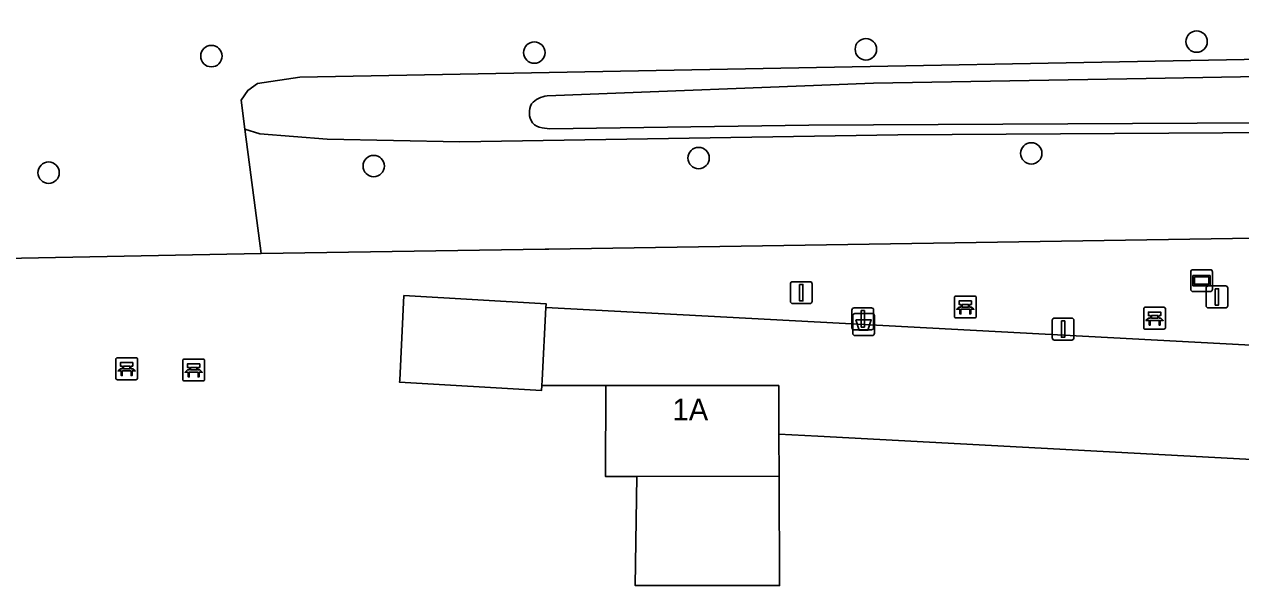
# Model space of a CAD drawing. Extents: x 161758 to 162722, y 384793 to 385405.
# Drawn here: x 162200.5 to 162256.1, y 385324.2 to 385349.9 of the extents above; entities that cross this region are included whole.
import ezdxf

# ---------------------------------------------------------------- set-up
doc = ezdxf.new("R2010")
doc.units = 0
for name, color, linetype in [('IMGEO_Afvalbak', 7, 'Continuous'), ('IMGEO_Bank', 7, 'Continuous'), ('IMGEO_Boom', 7, 'Continuous'), ('IMGEO_Groenvoorziening', 7, 'Continuous'), ('IMGEO_Lichtmast', 7, 'Continuous'), ('IMGEO_Oever', 7, 'Continuous'), ('IMGEO_Pand', 7, 'Continuous'), ('IMGEO_Pand_nummerreeks', 7, 'Continuous'), ('IMGEO_Verklikker', 7, 'Continuous'), ('IMGEO_Voetpad_open', 7, 'Continuous'), ('IMGEO_Waterloop', 7, 'Continuous')]:
    doc.layers.add(name, color=color, linetype=linetype)

msp = doc.modelspace()

# ---------------------------------------------------------------- linework, layer by layer
at = {"layer": 'IMGEO_Afvalbak'}
for p, q in [((162238.462, 385336.656), (162239.252, 385336.656)), ((162239.252, 385336.656), (162238.462, 385336.656)), ((162238.362, 385335.756), (162238.362, 385336.556)), ((162238.362, 385336.556), (162238.362, 385335.756)), ((162239.352, 385336.556), (162239.352, 385335.756)), ((162239.352, 385335.756), (162239.352, 385336.556)), ((162239.252, 385335.656), (162238.462, 385335.656)), ((162238.462, 385335.656), (162239.252, 385335.656))]:
    msp.add_line(p, q, dxfattribs=at)
msp.add_lwpolyline([(162238.505, 385336.37), (162239.209, 385336.37), (162239.06, 385335.9), (162238.654, 385335.9), (162238.505, 385336.37)], dxfattribs=at)
for centre, start, end in [((162238.462, 385336.556), 90, 180), ((162238.462, 385336.556), 90, 180), ((162239.252, 385336.556), 0, 90), ((162239.252, 385336.556), 360, 90), ((162238.462, 385335.756), 180, 270), ((162238.462, 385335.756), 180, 270), ((162239.252, 385335.756), 270, 0), ((162239.252, 385335.756), 270, 0)]:
    msp.add_arc(centre, 0.1, start, end, dxfattribs=at)
at = {"layer": 'IMGEO_Bank'}
for p, q in [((162243.01, 385336.531), (162243.01, 385337.372)), ((162243.01, 385337.372), (162243.01, 385336.531)), ((162243.085, 385337.456), (162243.926, 385337.456)), ((162243.926, 385337.456), (162243.085, 385337.456)), ((162244.01, 385337.381), (162244.01, 385336.54)), ((162244.01, 385336.54), (162244.01, 385337.381)), ((162243.707, 385336.854), (162243.314, 385336.854)), ((162243.319, 385336.962), (162243.319, 385337.068)), ((162243.363, 385337.068), (162243.363, 385336.962)), ((162243.651, 385337.074), (162243.369, 385337.074)), ((162243.369, 385336.956), (162243.651, 385336.956)), ((162243.657, 385336.962), (162243.657, 385337.068)), ((162243.701, 385337.068), (162243.701, 385336.962)), ((162251.66, 385336.021), (162251.66, 385336.862)), ((162251.66, 385336.862), (162251.66, 385336.021)), ((162251.735, 385336.946), (162252.576, 385336.946)), ((162252.576, 385336.946), (162251.735, 385336.946)), ((162252.66, 385336.871), (162252.66, 385336.03)), ((162252.66, 385336.03), (162252.66, 385336.871)), ((162243.935, 385336.456), (162243.094, 385336.456)), ((162243.094, 385336.456), (162243.935, 385336.456)), ((162252.357, 385336.344), (162251.964, 385336.344)), ((162251.969, 385336.452), (162251.969, 385336.558)), ((162252.013, 385336.558), (162252.013, 385336.452)), ((162252.301, 385336.564), (162252.019, 385336.564)), ((162252.019, 385336.446), (162252.301, 385336.446)), ((162252.307, 385336.452), (162252.307, 385336.558)), ((162252.351, 385336.558), (162252.351, 385336.452)), ((162252.585, 385335.946), (162251.744, 385335.946)), ((162251.744, 385335.946), (162252.585, 385335.946)), ((162204.681, 385333.714), (162204.681, 385334.555)), ((162204.681, 385334.555), (162204.681, 385333.714)), ((162204.756, 385334.639), (162205.597, 385334.639)), ((162205.597, 385334.639), (162204.756, 385334.639)), ((162205.681, 385334.564), (162205.681, 385333.723)), ((162205.681, 385333.723), (162205.681, 385334.564)), ((162207.744, 385333.657), (162207.744, 385334.498)), ((162207.744, 385334.498), (162207.744, 385333.657)), ((162207.819, 385334.582), (162208.66, 385334.582)), ((162208.66, 385334.582), (162207.819, 385334.582)), ((162208.744, 385334.507), (162208.744, 385333.666)), ((162208.744, 385333.666), (162208.744, 385334.507)), ((162205.378, 385334.037), (162204.985, 385334.037)), ((162204.99, 385334.145), (162204.99, 385334.251)), ((162205.034, 385334.251), (162205.034, 385334.145)), ((162205.322, 385334.257), (162205.04, 385334.257)), ((162205.04, 385334.139), (162205.322, 385334.139)), ((162205.328, 385334.145), (162205.328, 385334.251)), ((162205.372, 385334.251), (162205.372, 385334.145)), ((162208.441, 385333.98), (162208.048, 385333.98)), ((162208.053, 385334.088), (162208.053, 385334.194)), ((162208.097, 385334.194), (162208.097, 385334.088)), ((162208.385, 385334.2), (162208.103, 385334.2)), ((162208.103, 385334.082), (162208.385, 385334.082)), ((162208.391, 385334.088), (162208.391, 385334.194)), ((162208.435, 385334.194), (162208.435, 385334.088)), ((162205.606, 385333.639), (162204.765, 385333.639)), ((162204.765, 385333.639), (162205.606, 385333.639)), ((162208.669, 385333.582), (162207.828, 385333.582)), ((162207.828, 385333.582), (162208.669, 385333.582))]:
    msp.add_line(p, q, dxfattribs=at)
for points in [[(162243.313, 385337.074), (162243.227, 385337.074), (162243.227, 385337.235), (162243.79, 385337.235), (162243.79, 385337.074), (162243.707, 385337.074)], [(162243.257, 385336.854), (162243.115, 385336.854), (162243.227, 385336.956), (162243.313, 385336.956)], [(162243.307, 385336.847), (162243.307, 385336.64), (162243.264, 385336.64), (162243.264, 385336.847)], [(162243.707, 385336.956), (162243.79, 385336.956), (162243.902, 385336.854), (162243.763, 385336.854)], [(162243.757, 385336.847), (162243.757, 385336.64), (162243.713, 385336.64), (162243.713, 385336.847)], [(162251.963, 385336.564), (162251.877, 385336.564), (162251.877, 385336.725), (162252.44, 385336.725), (162252.44, 385336.564), (162252.357, 385336.564)], [(162251.907, 385336.344), (162251.765, 385336.344), (162251.877, 385336.446), (162251.963, 385336.446)], [(162251.957, 385336.337), (162251.957, 385336.13), (162251.914, 385336.13), (162251.914, 385336.337)], [(162252.357, 385336.446), (162252.44, 385336.446), (162252.552, 385336.344), (162252.413, 385336.344)], [(162252.407, 385336.337), (162252.407, 385336.13), (162252.363, 385336.13), (162252.363, 385336.337)], [(162204.984, 385334.257), (162204.898, 385334.257), (162204.898, 385334.418), (162205.461, 385334.418), (162205.461, 385334.257), (162205.378, 385334.257)], [(162204.928, 385334.037), (162204.786, 385334.037), (162204.898, 385334.139), (162204.984, 385334.139)], [(162204.978, 385334.03), (162204.978, 385333.823), (162204.935, 385333.823), (162204.935, 385334.03)], [(162205.378, 385334.139), (162205.461, 385334.139), (162205.573, 385334.037), (162205.434, 385334.037)], [(162205.428, 385334.03), (162205.428, 385333.823), (162205.384, 385333.823), (162205.384, 385334.03)], [(162207.991, 385333.98), (162207.849, 385333.98), (162207.961, 385334.082), (162208.047, 385334.082)], [(162208.047, 385334.2), (162207.961, 385334.2), (162207.961, 385334.361), (162208.524, 385334.361), (162208.524, 385334.2), (162208.441, 385334.2)], [(162208.041, 385333.973), (162208.041, 385333.766), (162207.998, 385333.766), (162207.998, 385333.973)], [(162208.441, 385334.082), (162208.524, 385334.082), (162208.636, 385333.98), (162208.497, 385333.98)], [(162208.491, 385333.973), (162208.491, 385333.766), (162208.447, 385333.766), (162208.447, 385333.973)]]:
    msp.add_lwpolyline(points, dxfattribs=at)
for centre, radius, start, end in [((162243.088, 385337.378), 0.0779, 92.4484, 184.2845), ((162243.088, 385337.378), 0.0779, 92.4484, 184.2845), ((162243.932, 385337.378), 0.0779, 2.4484, 94.2845), ((162243.932, 385337.378), 0.0779, 2.4484, 94.2845), ((162243.257, 385336.847), 0.00671, 2.8957, 87.1043), ((162243.314, 385336.847), 0.00671, 92.8957, 177.1043), ((162243.312, 385337.067), 0.00671, 2.8957, 87.1043), ((162243.312, 385336.963), 0.00671, 272.8957, 357.1043), ((162243.369, 385337.067), 0.00671, 92.8957, 177.1043), ((162243.369, 385336.963), 0.00671, 182.8957, 267.1043), ((162243.651, 385337.067), 0.00671, 2.8957, 87.1043), ((162243.651, 385336.963), 0.00671, 272.8957, 357.1043), ((162243.708, 385337.067), 0.00671, 92.8957, 177.1043), ((162243.708, 385336.963), 0.00671, 182.8957, 267.1043), ((162243.706, 385336.847), 0.00671, 2.8957, 87.1043), ((162243.763, 385336.847), 0.00671, 92.8957, 177.1043), ((162251.738, 385336.868), 0.0779, 92.4484, 184.2845), ((162251.738, 385336.868), 0.0779, 92.4484, 184.2845), ((162252.582, 385336.868), 0.0779, 2.4484, 94.2845), ((162252.582, 385336.868), 0.0779, 2.4484, 94.2845), ((162243.088, 385336.534), 0.0779, 182.4484, 274.2845), ((162243.088, 385336.534), 0.0779, 182.4484, 274.2845), ((162243.932, 385336.534), 0.0779, 272.4484, 4.2845), ((162243.932, 385336.534), 0.0779, 272.4484, 4.2845), ((162251.907, 385336.337), 0.00671, 2.8957, 87.1043), ((162251.964, 385336.337), 0.00671, 92.8957, 177.1043), ((162251.962, 385336.557), 0.00671, 2.8957, 87.1043), ((162251.962, 385336.453), 0.00671, 272.8957, 357.1043), ((162252.019, 385336.557), 0.00671, 92.8957, 177.1043), ((162252.019, 385336.453), 0.00671, 182.8957, 267.1043), ((162252.301, 385336.557), 0.00671, 2.8957, 87.1043), ((162252.301, 385336.453), 0.00671, 272.8957, 357.1043), ((162252.358, 385336.557), 0.00671, 92.8957, 177.1043), ((162252.358, 385336.453), 0.00671, 182.8957, 267.1043), ((162252.356, 385336.337), 0.00671, 2.8957, 87.1043), ((162252.413, 385336.337), 0.00671, 92.8957, 177.1043), ((162251.738, 385336.024), 0.0779, 182.4484, 274.2845), ((162251.738, 385336.024), 0.0779, 182.4484, 274.2845), ((162252.582, 385336.024), 0.0779, 272.4484, 4.2845), ((162252.582, 385336.024), 0.0779, 272.4484, 4.2845), ((162204.759, 385334.561), 0.0779, 92.4484, 184.2845), ((162204.759, 385334.561), 0.0779, 92.4484, 184.2845), ((162205.603, 385334.561), 0.0779, 2.4484, 94.2845), ((162205.603, 385334.561), 0.0779, 2.4484, 94.2845), ((162207.822, 385334.504), 0.0779, 92.4484, 184.2845), ((162207.822, 385334.504), 0.0779, 92.4484, 184.2845), ((162208.666, 385334.504), 0.0779, 2.4484, 94.2845), ((162208.666, 385334.504), 0.0779, 2.4484, 94.2845), ((162204.928, 385334.03), 0.00671, 2.8957, 87.1043), ((162204.985, 385334.03), 0.00671, 92.8957, 177.1043), ((162204.983, 385334.25), 0.00671, 2.8957, 87.1043), ((162204.983, 385334.146), 0.00671, 272.8957, 357.1043), ((162205.04, 385334.25), 0.00671, 92.8957, 177.1043), ((162205.04, 385334.146), 0.00671, 182.8957, 267.1043), ((162205.322, 385334.25), 0.00671, 2.8957, 87.1043), ((162205.322, 385334.146), 0.00671, 272.8957, 357.1043), ((162205.379, 385334.25), 0.00671, 92.8957, 177.1043), ((162205.379, 385334.146), 0.00671, 182.8957, 267.1043), ((162205.377, 385334.03), 0.00671, 2.8957, 87.1043), ((162205.434, 385334.03), 0.00671, 92.8957, 177.1043), ((162207.991, 385333.973), 0.00671, 2.8957, 87.1043), ((162208.048, 385333.973), 0.00671, 92.8957, 177.1043), ((162208.046, 385334.193), 0.00671, 2.8957, 87.1043), ((162208.046, 385334.089), 0.00671, 272.8957, 357.1043), ((162208.103, 385334.193), 0.00671, 92.8957, 177.1043), ((162208.103, 385334.089), 0.00671, 182.8957, 267.1043), ((162208.385, 385334.193), 0.00671, 2.8957, 87.1043), ((162208.385, 385334.089), 0.00671, 272.8957, 357.1043), ((162208.442, 385334.193), 0.00671, 92.8957, 177.1043), ((162208.442, 385334.089), 0.00671, 182.8957, 267.1043), ((162208.44, 385333.973), 0.00671, 2.8957, 87.1043), ((162208.497, 385333.973), 0.00671, 92.8957, 177.1043), ((162204.759, 385333.717), 0.0779, 182.4484, 274.2845), ((162204.759, 385333.717), 0.0779, 182.4484, 274.2845), ((162205.603, 385333.717), 0.0779, 272.4484, 4.2845), ((162205.603, 385333.717), 0.0779, 272.4484, 4.2845), ((162207.822, 385333.66), 0.0779, 182.4484, 274.2845), ((162207.822, 385333.66), 0.0779, 182.4484, 274.2845), ((162208.666, 385333.66), 0.0779, 272.4484, 4.2845), ((162208.666, 385333.66), 0.0779, 272.4484, 4.2845)]:
    msp.add_arc(centre, radius, start, end, dxfattribs=at)
at = {"layer": 'IMGEO_Boom'}
for centre in [(162254.078, 385349.076), (162209.053, 385348.411), (162223.811, 385348.574), (162238.963, 385348.723), (162246.523, 385343.971), (162216.473, 385343.392), (162231.32, 385343.758), (162201.612, 385343.09)]:
    msp.add_circle(centre, 0.489, dxfattribs=at)
at = {"layer": 'IMGEO_Groenvoorziening'}
for points in [[(162150.256, 385338.217), (162211.326, 385339.4), (162210.576, 385345.078), (162210.407, 385346.397), (162210.716, 385346.847), (162211.162, 385347.162), (162213.09, 385347.455), (162274.995, 385348.608), (162275.287, 385348.966), (162275.287, 385349.716), (162281.73, 385349.862), (162282.898, 385349.07), (162282.9, 385348.722), (162317.058, 385348.931), (162338.302, 385349.603)], [(162280.054, 385345.054), (162240.431, 385344.814), (162220.411, 385344.502), (162214.349, 385344.623), (162211.26, 385344.857), (162210.576, 385345.078), (162211.326, 385339.4), (162224.309, 385339.601), (162224.475, 385339.604), (162280.127, 385340.465)], [(162280.127, 385340.465), (162224.475, 385339.604), (162224.309, 385339.601), (162211.326, 385339.4), (162150.256, 385338.217)], [(162269.369, 385329.305), (162236.772, 385331.057), (162234.99, 385331.156), (162234.998, 385329.231), (162235.019, 385324.236), (162228.418, 385324.247), (162228.492, 385329.215), (162227.065, 385329.212), (162227.072, 385333.378), (162224.155, 385333.38), (162224.142, 385333.149), (162217.656, 385333.521), (162217.662, 385333.622), (162217.855, 385337.476), (162224.348, 385337.109), (162224.339, 385336.928), (162269.685, 385334.516)]]:
    msp.add_lwpolyline(points, dxfattribs=at)
at = {"layer": 'IMGEO_Lichtmast'}
for p, q in [((162235.517, 385337.214), (162235.517, 385338.014)), ((162235.517, 385338.014), (162235.517, 385337.214)), ((162235.617, 385338.114), (162236.407, 385338.114)), ((162236.407, 385338.114), (162235.617, 385338.114)), ((162236.507, 385338.014), (162236.507, 385337.214)), ((162236.507, 385337.214), (162236.507, 385338.014)), ((162254.512, 385337.017), (162254.512, 385337.817)), ((162254.512, 385337.817), (162254.512, 385337.017)), ((162254.612, 385337.917), (162255.402, 385337.917)), ((162255.402, 385337.917), (162254.612, 385337.917)), ((162255.502, 385337.817), (162255.502, 385337.017)), ((162255.502, 385337.017), (162255.502, 385337.817)), ((162236.407, 385337.114), (162235.617, 385337.114)), ((162235.617, 385337.114), (162236.407, 385337.114)), ((162238.329, 385336.018), (162238.329, 385336.818)), ((162238.329, 385336.818), (162238.329, 385336.018)), ((162238.429, 385336.918), (162239.219, 385336.918)), ((162239.219, 385336.918), (162238.429, 385336.918)), ((162239.319, 385336.818), (162239.319, 385336.018)), ((162239.319, 385336.018), (162239.319, 385336.818)), ((162255.402, 385336.917), (162254.612, 385336.917)), ((162254.612, 385336.917), (162255.402, 385336.917)), ((162247.479, 385335.551), (162247.479, 385336.351)), ((162247.479, 385336.351), (162247.479, 385335.551)), ((162247.579, 385336.451), (162248.369, 385336.451)), ((162248.369, 385336.451), (162247.579, 385336.451)), ((162248.469, 385336.351), (162248.469, 385335.551)), ((162248.469, 385335.551), (162248.469, 385336.351)), ((162239.219, 385335.918), (162238.429, 385335.918)), ((162238.429, 385335.918), (162239.219, 385335.918)), ((162248.369, 385335.451), (162247.579, 385335.451)), ((162247.579, 385335.451), (162248.369, 385335.451))]:
    msp.add_line(p, q, dxfattribs=at)
for points in [[(162235.937, 385337.989), (162236.087, 385337.989), (162236.087, 385337.239), (162235.937, 385337.239), (162235.937, 385337.989)], [(162254.932, 385337.792), (162255.082, 385337.792), (162255.082, 385337.042), (162254.932, 385337.042), (162254.932, 385337.792)], [(162238.749, 385336.793), (162238.899, 385336.793), (162238.899, 385336.043), (162238.749, 385336.043), (162238.749, 385336.793)], [(162247.899, 385336.326), (162248.049, 385336.326), (162248.049, 385335.576), (162247.899, 385335.576), (162247.899, 385336.326)]]:
    msp.add_lwpolyline(points, dxfattribs=at)
for centre, start, end in [((162235.617, 385338.014), 90, 180), ((162235.617, 385338.014), 90, 180), ((162236.407, 385338.014), 0, 90), ((162236.407, 385338.014), 360, 90), ((162254.612, 385337.817), 90, 180), ((162254.612, 385337.817), 90, 180), ((162255.402, 385337.817), 0, 90), ((162255.402, 385337.817), 360, 90), ((162235.617, 385337.214), 180, 270), ((162235.617, 385337.214), 180, 270), ((162236.407, 385337.214), 270, 0), ((162236.407, 385337.214), 270, 0), ((162238.429, 385336.818), 90, 180), ((162238.429, 385336.818), 90, 180), ((162239.219, 385336.818), 0, 90), ((162239.219, 385336.818), 360, 90), ((162254.612, 385337.017), 180, 270), ((162254.612, 385337.017), 180, 270), ((162255.402, 385337.017), 270, 0), ((162255.402, 385337.017), 270, 0), ((162247.579, 385336.351), 90, 180), ((162247.579, 385336.351), 90, 180), ((162248.369, 385336.351), 0, 90), ((162248.369, 385336.351), 360, 90), ((162238.429, 385336.018), 180, 270), ((162238.429, 385336.018), 180, 270), ((162239.219, 385336.018), 270, 0), ((162239.219, 385336.018), 270, 0), ((162247.579, 385335.551), 180, 270), ((162247.579, 385335.551), 180, 270), ((162248.369, 385335.551), 270, 0), ((162248.369, 385335.551), 270, 0)]:
    msp.add_arc(centre, 0.1, start, end, dxfattribs=at)
at = {"layer": 'IMGEO_Oever'}
for points in [[(162317.058, 385348.931), (162282.9, 385348.722), (162282.898, 385349.07), (162281.73, 385349.862), (162275.287, 385349.716), (162275.287, 385348.966), (162274.995, 385348.608), (162213.09, 385347.455), (162211.162, 385347.162), (162210.716, 385346.847), (162210.407, 385346.397), (162210.576, 385345.078), (162211.26, 385344.857), (162214.349, 385344.623), (162220.411, 385344.502), (162240.431, 385344.814), (162280.054, 385345.054), (162305.72, 385345.824), (162336.125, 385346.248)], [(162224.398, 385346.596), (162239.318, 385347.175), (162251.771, 385347.393), (162269.02, 385347.694), (162274.973, 385347.719), (162275.518, 385347.774), (162275.899, 385348.209), (162275.887, 385348.625), (162275.872, 385349.134), (162279.818, 385349.243), (162281.859, 385349.134), (162282.304, 385348.718), (162282.703, 385348.345), (162282.866, 385347.991), (162287.166, 385348.127), (162307.576, 385348.323), (162323.198, 385348.502), (162338.294, 385348.997), (162351.286, 385348.992), (162353.153, 385349.249), (162358.001, 385349.112), (162373.931, 385349.337), (162383.565, 385349.579)], [(162283.34, 385345.718), (162274.802, 385345.457), (162236.361, 385345.265), (162224.504, 385345.093), (162224.163, 385345.139)]]:
    msp.add_lwpolyline(points, dxfattribs=at)
for centre, radius, start, end in [((162224.463, 385345.845), 0.881, 153.3733, 213.0371), ((162224.565, 385345.346), 1.261, 97.6286, 134.8649), ((162224.238, 385345.821), 0.686, 221.6578, 263.7564)]:
    msp.add_arc(centre, radius, start, end, dxfattribs=at)
at = {"layer": 'IMGEO_Pand'}
for points in [[(162224.348, 385337.109), (162217.855, 385337.476), (162217.662, 385333.622), (162217.656, 385333.521), (162224.142, 385333.149), (162224.155, 385333.38), (162224.17, 385333.623), (162224.339, 385336.928)], [(162234.979, 385333.373), (162227.072, 385333.378), (162227.065, 385329.212), (162228.492, 385329.215), (162234.998, 385329.231), (162234.99, 385331.156)]]:
    msp.add_lwpolyline(points, close=True, dxfattribs=at)
at = {"layer": 'IMGEO_Verklikker'}
for p, q in [((162253.809, 385337.761), (162253.809, 385338.561)), ((162253.809, 385338.561), (162253.809, 385337.761)), ((162253.909, 385338.661), (162254.699, 385338.661)), ((162254.699, 385338.661), (162253.909, 385338.661)), ((162254.799, 385338.561), (162254.799, 385337.761)), ((162254.799, 385337.761), (162254.799, 385338.561)), ((162254.699, 385337.661), (162253.909, 385337.661)), ((162253.909, 385337.661), (162254.699, 385337.661))]:
    msp.add_line(p, q, dxfattribs=at)
for points in [[(162253.91, 385338.393), (162254.698, 385338.393), (162254.698, 385337.929), (162253.91, 385337.929), (162253.91, 385338.393)], [(162253.975, 385338.328), (162253.975, 385337.994), (162254.633, 385337.994), (162254.633, 385338.328), (162253.975, 385338.328)]]:
    msp.add_lwpolyline(points, dxfattribs=at)
for centre, start, end in [((162253.909, 385338.561), 90, 180), ((162253.909, 385338.561), 90, 180), ((162254.699, 385338.561), 0, 90), ((162254.699, 385338.561), 360, 90), ((162253.909, 385337.761), 180, 270), ((162253.909, 385337.761), 180, 270), ((162254.699, 385337.761), 270, 0), ((162254.699, 385337.761), 270, 0)]:
    msp.add_arc(centre, 0.1, start, end, dxfattribs=at)
at = {"layer": 'IMGEO_Voetpad_open'}
for points in [[(162269.572, 385332.969), (162269.685, 385334.516), (162224.339, 385336.928), (162224.17, 385333.623), (162224.155, 385333.38), (162227.072, 385333.378), (162234.979, 385333.373), (162234.99, 385331.156), (162236.772, 385331.057), (162269.369, 385329.305)], [(162234.998, 385329.231), (162228.492, 385329.215), (162228.418, 385324.247), (162235.019, 385324.236)]]:
    msp.add_lwpolyline(points, close=True, dxfattribs=at)
at = {"layer": 'IMGEO_Waterloop'}
for points in [[(162383.565, 385349.579), (162373.931, 385349.337), (162358.001, 385349.112), (162353.153, 385349.249), (162351.286, 385348.992), (162338.294, 385348.997), (162323.198, 385348.502), (162307.576, 385348.323), (162287.166, 385348.127), (162282.866, 385347.991), (162282.703, 385348.345), (162282.304, 385348.718), (162281.859, 385349.134), (162279.818, 385349.243), (162275.872, 385349.134), (162275.887, 385348.625), (162275.899, 385348.209), (162275.518, 385347.774), (162274.973, 385347.719), (162269.02, 385347.694), (162251.771, 385347.393), (162239.318, 385347.175), (162224.398, 385346.596)], [(162224.163, 385345.139), (162224.504, 385345.093), (162236.361, 385345.265), (162274.802, 385345.457), (162283.34, 385345.718), (162286.246, 385346.407), (162288.552, 385345.878), (162307.07, 385346.519), (162328.213, 385346.616), (162345.259, 385347.069), (162358.461, 385347.328), (162368.416, 385347.343), (162374.704, 385347.469), (162380.201, 385347.663), (162383.442, 385347.777)]]:
    msp.add_lwpolyline(points, dxfattribs=at)
for centre, radius, start, end in [((162224.463, 385345.845), 0.881, 153.3733, 213.0371), ((162224.565, 385345.346), 1.261, 97.6286, 134.8649), ((162224.238, 385345.821), 0.686, 221.6578, 263.7564)]:
    msp.add_arc(centre, radius, start, end, dxfattribs=at)

# ---------------------------------------------------------------- texts
at = {"layer": 'IMGEO_Pand_nummerreeks'}
msp.add_text('1A', height=1, dxfattribs=at).set_placement((162230.125, 385331.776))

doc.saveas('drawing.dxf')
